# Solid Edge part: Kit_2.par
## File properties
Author: bmolnar
Last saved by: bmolnar
Revision: 77
Sűrűség: 0,000 kg/m^3
Pontosság: 0,990
Username: bmolnar
Dokumentum tartalom típus: 0
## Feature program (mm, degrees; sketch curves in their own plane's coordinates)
base feature "unnamed BaseFeature 1"
thread "unnamed Thread 1"
thread "unnamed Thread 2"
thread "unnamed Thread 3"
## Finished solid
Body 1: solid body, 326 faces, 784 edges, 476 vertices.
  Faces by surface: plane 151, cylinder 76, swept 56, cone 31, torus 11, spline 1
  Edges by curve: line 462, circle 171, spline 120, ellipse 28, curve on surface 2, intersection 1
Bounding box of the edges (mm; curved faces can reach further): 113.300 x 113.300 x 19.500, from (-56.65, -56.65, -97.5) to (56.65, 56.65, -78).
Cylindrical faces by radius (mm): R0.2 x48, R0.2006 x2, R0.2007 x2, R3 x1, R4.188 x2, R4.283 x1, R6.35 x4, R6.55 x4, R6.75 x2, R7 x2, R8 x2, R12.8 x1, R13.45 x1, R14 x1, R14.9 x1, R15 x1, R24.634 x1
Conical faces (half-angle, radius in mm at the cone's reference point): 0.5 deg R12.25 x4, 0.5 deg R35 x2, 3 deg R14.95 x1, 7 deg R14.2695 x1, 14 deg R12.65 x1, 14 deg R13.057 x1, 15 deg R7.067 x4, 15 deg R7.933 x4, 17 deg R12.65 x1, 23 deg R13.4211 x1, 42.5 deg R12.637 x1, 45 deg R4.588 x4, 45 deg R8.15 x2, 45 deg R13.6 x1, 84 deg R13.012 x1, 85 deg R14.6625 x1, 87 deg R12.7157 x1
Toroidal faces (ring radius, tube radius in mm): R6.05 r0.3 x2, R6.15 r0.2 x6, R13.4008 r0.225 x1, R13.8914 r0.325 x1, R14.7 r0.2 x1
Planar faces by outward normal: +x 17, +y 16, +z 2, -x 14, -y 18, -z 21, oblique 63
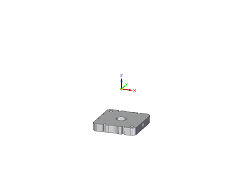
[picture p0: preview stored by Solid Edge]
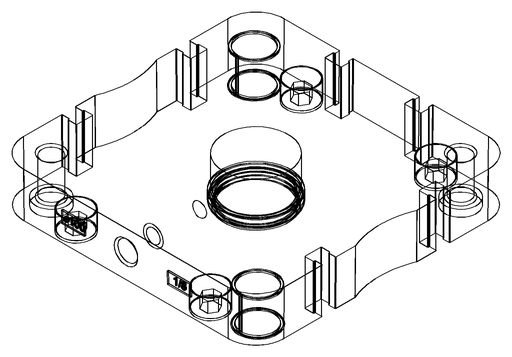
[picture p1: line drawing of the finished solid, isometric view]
